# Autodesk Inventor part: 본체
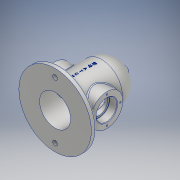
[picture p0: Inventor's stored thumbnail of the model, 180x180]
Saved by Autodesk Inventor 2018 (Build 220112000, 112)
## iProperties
Created: 2019-11
Part Number: 본체
Material: 알루미늄 6061
Document SubType Name: Modeling
Designer: Administrator
Density: 2.7 g/cm^3
Appearance: 알루미늄 - 평지
Mass: 1106.21 g
Surface Area: 883.176 cm^2
Volume: 409.708 cm^3
Author: Administrator
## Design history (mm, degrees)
sketch "스케치1"
  geometry: C1 r 40 at (0, 0); 1 further point
  constraints: 1 centre point, 1 coincident
  dimensions: "d0" = 80 diameter of C1
extrude "돌출1" new body sketch "스케치1" stored distance "d1" = 80; taper "d2" = 0 deg
sketch "스케치2"
  geometry: C1 r 70 at (0, 0); 1 further point
  constraints: 1 centre point, 1 coincident
  dimensions: "d3" = 140 diameter of C1
extrude "돌출2" join sketch "스케치2" distance "d4" = 10; taper "d5" = 0 deg
sketch "스케치3"
  geometry: L1 (0, 40)-(2.348, 40); L2 (2.348, 40)-(40, 40); L3 (0, 40)-(0, 80); L4 (40, 40)-(-40, 40) reference; L5 (0, 83.321)-(0, 31.189); A1 r 40 centre (0, 40) between (40, 40) and (0, 80); 1 further point
  constraints: 8 end point, 2 point on circle, 1 centre point, 1 collinear, 1 perpendicular, 1 vertical
revolve "회전1" sketch "스케치3" stored, may be unused: angle "d6" = 90 deg
sketch "스케치4"
  geometry: L1 (-50, 70)-(-50, -70) reference; L2 (-50, 0)-(0, 0); C1 r 31 at (0, 0)
  constraints: 2 end point, 1 centre point, 1 coincident, 1 horizontal, 1 midpoint
  dimensions: "d7" = 50 distance of L2.start L2.end (derived); "d8" = 62 diameter of C1
extrude "돌출3" join sketch "스케치4" stored distance "d9" = 100; taper "d10" = 0 deg
sketch "스케치5"
  geometry: C1 r 30 at (0, 0); 1 further point
  constraints: 1 centre point, 1 coincident
  dimensions: "d11" = 60 diameter of C1
extrude "돌출4" cut sketch "스케치5" distance "d12" = 90; taper "d13" = 0 deg
sketch "스케치6"
  geometry: L1 (30, 40)-(-30, 40) reference; L2 (0, 40)-(0, 70); L3 (30, 40)-(0, 40); L4 (0, 73.114)-(0, 27.155); A1 r 30 centre (0, 40) between (30, 40) and (0, 70); 1 further point
  constraints: 7 end point, 3 point on circle, 2 vertical, 1 centre point, 1 coincident, 1 collinear, 1 midpoint, 1 point on line
revolve "회전2" sketch "스케치6" stored, may be unused: angle "d15" = 90 deg
sketch "스케치7"
  geometry: C1 r 16.5 at (0, 0); 1 further point
  constraints: 1 centre point, 1 coincident
  dimensions: "d16" = 33 diameter of C1
extrude "돌출5" cut sketch "스케치7" distance "d17" = 100; taper "d18" = 0 deg
sketch "스케치8"
  geometry: C1 r 20 at (0, 0); 1 further point
  constraints: 1 centre point, 1 coincident
  dimensions: "d19" = 40 diameter of C1
extrude "돌출6" cut sketch "스케치8" distance "d20" = 15; taper "d21" = 0 deg
sketch "스케치9"
  geometry: L1 (0, 0)-(0, 85)
  constraints: 2 end point, 1 vertical
  dimensions: "d22" = 85 distance of L1.start L1.end
node "작업 평면1"
sketch "스케치10"
  geometry: C1 r 7.5 at (0, 0); 1 further point
  constraints: 1 centre point, 1 coincident
  dimensions: "d23" = 15 diameter of C1
extrude "돌출7" join sketch "스케치10" stored distance "d24" = 15; taper "d25" = 0 deg
sketch "스케치11"
  geometry: C1 r 4.5 at (0, 55); C2 r 4.5 at (0, -55); 1 further point
  constraints: 2 centre point
  dimensions: "d27" = 9 diameter of C1; "d28" = 9 diameter of C2
extrude "돌출8" cut sketch "스케치11" distance "d29" = 15; taper "d30" = 0 deg
sketch "스케치12"
  geometry: 2 further points
  constraints: 1 coincident
hole "구멍1" sketch "스케치12" at (0, 0) diameter "d31" = 4.917; stored, may be unused: countersink angle "d35" = 90 deg, drill point angle "d37" = 118 deg; dims "d32" = 12, "d33" = 4, "d34" = 2, "d36" = 17.1
sketch "스케치13"
  geometry: A1 r 26 centre (0, 0) between (0, 26) and (-26, 0); 3 further points
  constraints: 4 point on circle, 1 centre point, 1 coincident
  dimensions: "d38" = 52 diameter of A1
hole "구멍2" sketch "스케치13" at (0, 26), (-26, 0), (0, -26), (26, 0) diameter "d39" = 3.242; stored, may be unused: countersink angle "d43" = 90 deg, drill point angle "d45" = 118 deg; dims "d40" = 8, "d41" = 4, "d42" = 2, "d44" = 10
sketch "스케치14"
  geometry: L1 (-50, 70)-(-50, -70) reference; L2 (0, 70)-(0, 78.186); 1 further point
  constraints: 2 end point
node "작업 평면2"
sketch "스케치15"
  geometry: L1 (-3.474, 28.821)-(3.474, 28.821); L2 (3.474, 28.821)-(3.474, -28.821); L3 (3.474, -28.821)-(-3.474, -28.821); L4 (-3.474, -28.821)-(-3.474, 28.821); L5 (-3.474, 0)-(3.474, 0); 2 further points
  constraints: 3 midpoint, 2 coincident, 2 end point, 2 other
feature "엠보싱1" sketch "스케치15" dims "d8" = 62, "d47" = 0.5, "d48" = 0
fillet "모깎기1" dims "d49" = 3
fillet "모깎기2" dims "d50" = 3
fillet "모깎기3" dims "d51" = 0.3
chamfer "모따기1" distance "d52" = 1; stored, may be unused: second distance "d53" = 2, angle "d54" = 45 deg
node "솔리드1"
mirror "미러1"
mirror "미러2"
